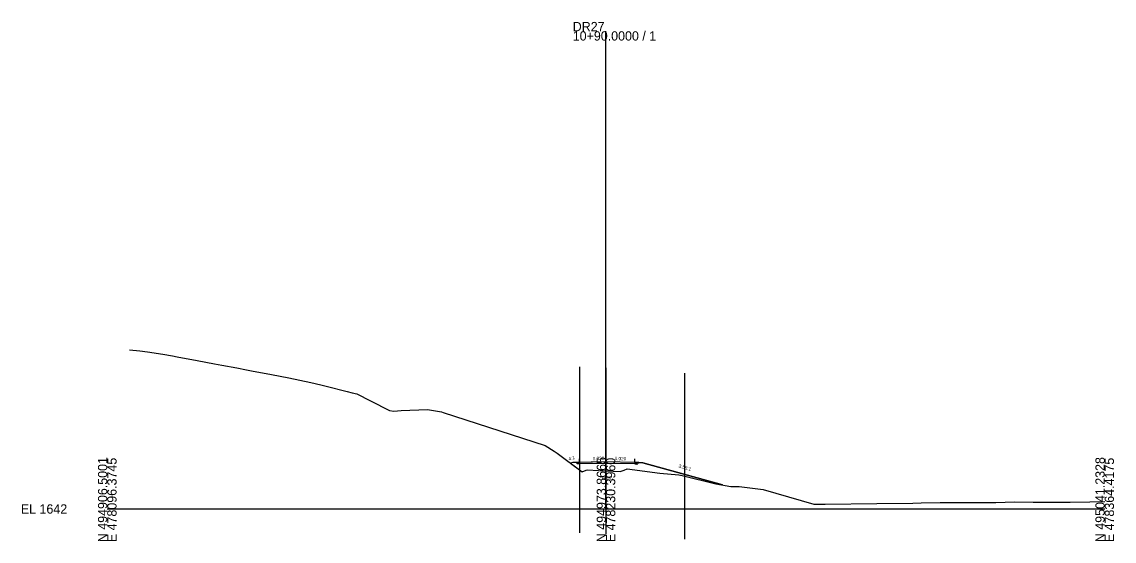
# Model space of a CAD drawing. Extents: x -26 to 478410, y -18 to 495058.
# Drawn here: x -25.7 to 302.8, y 1490.3 to 1646.6 of the extents above; entities that cross this region are included whole.
import ezdxf

# ---------------------------------------------------------------- set-up
doc = ezdxf.new("R2010")
doc.units = 0
for name, color, linetype in [('Exist Cross Section Cell', 7, 'Continuous'), ('Exist XS Center Line Elevation Label', 7, 'Continuous'), ('Exist XS Ground Line', 7, 'Continuous'), ('Prop XS Ditch Slope Text', 7, 'Continuous'), ('Prop XS Dump Level', 7, 'Continuous'), ('Prop XS Earthwork Shape', 7, 'Continuous'), ('Prop XS EOT Tick Mark', 7, 'Continuous'), ('Prop XS Finish Grade', 7, 'Continuous'), ('Prop XS Finish Grade Earthwork', 7, 'Continuous'), ('Prop XS Finish Grade Pavement', 7, 'Continuous'), ('Prop XS Pvmt Edge Slope', 7, 'Continuous'), ('Prop XS SE Text', 7, 'Continuous'), ('Prop XS Shoulder Borrow Shape', 7, 'Continuous'), ('Prop XS Side Slope Text', 7, 'Continuous'), ('Prop XS Subgrade Earthwork', 7, 'Continuous'), ('Scratch_Level_4', 7, 'Continuous')]:
    doc.layers.add(name, color=color, linetype=linetype)

msp = doc.modelspace()

# ---------------------------------------------------------------- linework, layer by layer
at = {"layer": 'Exist Cross Section Cell'}
for p, q in [((150, 1500), (150, 1643.75)), ((0, 1500), (150, 1500)), ((150, 1500), (300, 1500))]:
    msp.add_line(p, q, dxfattribs=at)
at = {"layer": 'Exist XS Ground Line'}
msp.add_lwpolyline([(6.73, 1547.92), (9.83, 1547.61), (12.12, 1547.28), (16.67, 1546.55), (19.57, 1546.04), (21.02, 1545.76), (27.02, 1544.68), (32.22, 1543.72), (34.47, 1543.29), (38.95, 1542.43), (41.92, 1541.83), (43.41, 1541.59), (49.37, 1540.5), (54.6, 1539.43), (61.22, 1538.03), (64.27, 1537.37), (65.8, 1536.95), (72.2, 1535.39), (73.68, 1534.97), (75.04, 1534.6), (79.14, 1532.57), (84.84, 1529.62), (86.17, 1529.47), (88.37, 1529.58), (96.32, 1529.89), (100.57, 1529.2), (101.01, 1529.07), (131.67, 1519.12), (134.43, 1517.44), (135.35, 1516.75), (142.81, 1511.21), (144.03, 1511.66), (144.39, 1511.78), (147.76, 1511.62), (150, 1511.5), (154.29, 1511.26), (155.42, 1511.68), (156.41, 1512.04), (166.22, 1510.74), (171.9, 1510.31), (172.94, 1510.02), (183.02, 1507.57), (187.58, 1506.78), (190.01, 1506.77), (197.24, 1505.84), (212.48, 1501.43), (214.07, 1501.44), (215.93, 1501.44), (231.45, 1501.62), (242.24, 1501.79), (244.78, 1501.8), (250.5, 1501.92), (256.1, 1501.95), (257.96, 1501.98), (261.65, 1501.98), (267.3, 1501.99), (272.86, 1502.11), (278.49, 1502.03), (280.31, 1502.02), (283.92, 1502.04), (288.01, 1502.04), (289.65, 1502.06), (295.51, 1502.17), (300, 1502.22)], dxfattribs=at)
at = {"layer": 'Prop XS Dump Level'}
for p, q in [((145.5, 1514.16), (150, 1514.25)), ((150, 1514.25), (158.7, 1514.08))]:
    msp.add_line(p, q, dxfattribs=at)
at = {"layer": 'Prop XS Earthwork Shape'}
msp.add_lwpolyline([(139.36, 1513.77), (142.81, 1511.21), (144.03, 1511.66), (144.39, 1511.78), (147.76, 1511.62), (150, 1511.5), (154.29, 1511.26), (155.42, 1511.68), (156.41, 1512.04), (166.22, 1510.74), (171.9, 1510.31), (172.94, 1510.02), (183.02, 1507.57), (185.02, 1507.23), (161.08, 1513.92), (159.92, 1513.99), (159.36, 1513.52), (158.7, 1513.53), (150, 1513.68), (142, 1513.55), (141.45, 1513.54), (140.98, 1514.01), (140, 1513.93)], close=True, dxfattribs=at)
at = {"layer": 'Prop XS EOT Tick Mark'}
for p, q in [((142, 1514.09), (142, 1515.09)), ((158.7, 1514.08), (158.7, 1515.08))]:
    msp.add_line(p, q, dxfattribs=at)
at = {"layer": 'Prop XS Finish Grade'}
for p, q in [((142, 1514.09), (140.98, 1514.01)), ((158.7, 1514.08), (159.92, 1513.99))]:
    msp.add_line(p, q, dxfattribs=at)
at = {"layer": 'Prop XS Finish Grade Earthwork'}
for p, q in [((140, 1513.93), (139.36, 1513.77)), ((140.98, 1514.01), (140, 1513.93)), ((159.92, 1513.99), (161.08, 1513.92)), ((161.08, 1513.92), (185.02, 1507.23))]:
    msp.add_line(p, q, dxfattribs=at)
at = {"layer": 'Prop XS Finish Grade Pavement'}
for p, q in [((142, 1514.09), (150, 1514.25)), ((150, 1514.25), (158.7, 1514.08))]:
    msp.add_line(p, q, dxfattribs=at)
at = {"layer": 'Prop XS Pvmt Edge Slope'}
for p, q in [((142, 1514.09), (141.45, 1513.54)), ((158.7, 1514.08), (159.36, 1513.52))]:
    msp.add_line(p, q, dxfattribs=at)
at = {"layer": 'Prop XS Shoulder Borrow Shape'}
for points in [[(142, 1514.09), (141.45, 1513.54), (140.98, 1514.01)], [(159.36, 1513.52), (159.92, 1513.99), (158.7, 1514.08)]]:
    msp.add_lwpolyline(points, close=True, dxfattribs=at)
at = {"layer": 'Prop XS Subgrade Earthwork'}
for p, q in [((141.45, 1513.54), (140.98, 1514.01)), ((142, 1513.55), (141.45, 1513.54)), ((150, 1513.68), (142, 1513.55)), ((158.7, 1513.53), (150, 1513.68)), ((158.7, 1513.53), (159.36, 1513.52)), ((159.36, 1513.52), (159.92, 1513.99))]:
    msp.add_line(p, q, dxfattribs=at)
at = {"layer": 'Scratch_Level_4'}
for p, q in [((142, 1542.8), (142, 1492.8)), ((150, 1542.5), (150, 1492.5)), ((173.58, 1540.86), (173.58, 1490.86))]:
    msp.add_line(p, q, dxfattribs=at)

# ---------------------------------------------------------------- texts
at = {"layer": 'Exist Cross Section Cell'}
for s, p in [('DR27', (140, 1643.75)), ('10+90.0000 / 1', (140, 1640.95)), ('EL 1642', (-26, 1498.6))]:
    msp.add_text(s, height=2.8, dxfattribs=at).set_placement(p)
for s, p in [('N 494906.5001', (0, 1490)), ('E 478096.3745', (2.8, 1490)), ('N 494973.8665', (150, 1490)), ('E 478230.3960', (152.8, 1490)), ('N 495041.2328', (300, 1490)), ('E 478364.4175', (302.8, 1490))]:
    msp.add_text(s, height=2.8, rotation=90, dxfattribs=at).set_placement(p)
at = {"layer": 'Exist XS Center Line Elevation Label'}
msp.add_text('1653.50', height=0.75, dxfattribs=at).set_placement((148.19, 1508.75))
at = {"layer": 'Prop XS Ditch Slope Text'}
msp.add_text('4:1', height=1, rotation=14.0362, dxfattribs=at).set_placement((138.85, 1514.58))
at = {"layer": 'Prop XS Dump Level'}
for p in [(140, 1513.89), (161.08, 1513.88)]:
    msp.add_text('Case1', height=0.04, dxfattribs=at).set_placement(p)
at = {"layer": 'Prop XS SE Text'}
for rotation, p in [(1.1458, (146.02, 1514.67)), (358.8542, (152.61, 1514.7))]:
    msp.add_text('0.020', height=1, rotation=rotation, dxfattribs=at).set_placement(p)
at = {"layer": 'Prop XS Side Slope Text'}
msp.add_text('3.58:1', height=1, rotation=344.3846, dxfattribs=at).set_placement((171.77, 1512.49))

doc.saveas('drawing.dxf')
